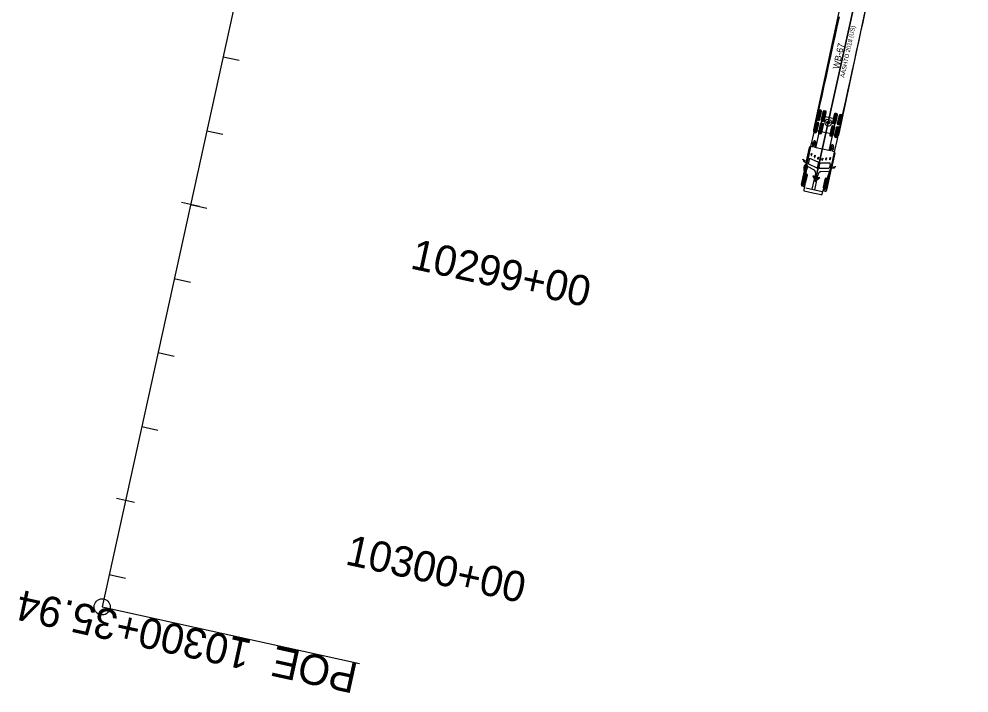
# Model space of a CAD drawing. Extents: x -69 to 14108008, y -6 to 8640172.
# Drawn here: x 14107520.5 to 14107834.1, y 8638940.1 to 8639162.5 of the extents above; entities that cross this region are included whole.
import ezdxf

# ---------------------------------------------------------------- set-up
doc = ezdxf.new("R2010")
doc.units = 0
for name, color, linetype in [('Alignment', 7, 'Continuous'), ('AutoTurn', 7, 'Continuous'), ('TextAlignment', 7, 'Continuous'), ('TextAlignmentLrg', 7, 'Continuous'), ('TextAlignmentSml', 7, 'Continuous')]:
    doc.layers.add(name, color=color, linetype=linetype)

msp = doc.modelspace()

# ---------------------------------------------------------------- linework, layer by layer
at = {"layer": 'Alignment'}
msp.add_line((14107732.61, 8639808.61), (14107547.95, 8638968.47), dxfattribs=at)
at = {"layer": 'AutoTurn'}
for p, q in [((14107783.36, 8639108.95), (14107834.09, 8639339.91)), ((14107834.09, 8639339.91), (14107783.36, 8639108.95)), ((14107783.91, 8639129.07), (14107784.7, 8639132.65)), ((14107784.14, 8639129.02), (14107784.92, 8639132.6)), ((14107784.36, 8639128.97), (14107785.15, 8639132.55)), ((14107785.53, 8639128.71), (14107786.31, 8639132.3)), ((14107785.75, 8639128.66), (14107786.54, 8639132.25)), ((14107785.97, 8639128.62), (14107786.76, 8639132.2)), ((14107789.22, 8639127.9), (14107790.01, 8639131.48)), ((14107789.44, 8639127.85), (14107790.23, 8639131.43)), ((14107789.67, 8639127.8), (14107790.46, 8639131.38)), ((14107790.83, 8639127.55), (14107791.62, 8639131.13)), ((14107791.06, 8639127.5), (14107791.84, 8639131.08)), ((14107791.28, 8639127.45), (14107792.07, 8639131.03)), ((14107783.01, 8639124.97), (14107783.8, 8639128.55)), ((14107783.24, 8639124.92), (14107784.02, 8639128.5)), ((14107783.46, 8639124.87), (14107784.25, 8639128.45)), ((14107784.62, 8639124.61), (14107785.41, 8639128.19)), ((14107784.85, 8639124.56), (14107785.63, 8639128.14)), ((14107785.07, 8639124.51), (14107785.86, 8639128.09)), ((14107788.58, 8639129), (14107787, 8639129.34)), ((14107788.32, 8639123.8), (14107789.11, 8639127.38)), ((14107788.54, 8639123.75), (14107789.33, 8639127.33)), ((14107788.77, 8639123.7), (14107789.55, 8639127.28)), ((14107789.93, 8639123.45), (14107790.72, 8639127.03)), ((14107790.15, 8639123.4), (14107790.94, 8639126.98)), ((14107790.38, 8639123.35), (14107791.17, 8639126.93)), ((14107781.83, 8639120.55), (14107782.66, 8639120.37)), ((14107781.96, 8639117.63), (14107782.12, 8639118.16)), ((14107782.12, 8639118.16), (14107782.2, 8639118.14)), ((14107782.2, 8639118.14), (14107782.12, 8639117.6)), ((14107783.6, 8639120.16), (14107787.83, 8639119.23)), ((14107788.78, 8639119.02), (14107789.6, 8639118.84)), ((14107779.54, 8639115.76), (14107779.52, 8639115.78)), ((14107779.57, 8639115.76), (14107779.54, 8639115.76)), ((14107780.34, 8639115.05), (14107780.32, 8639114.95)), ((14107780.83, 8639117.25), (14107780.54, 8639114.46)), ((14107781.3, 8639116.17), (14107781.06, 8639115.07)), ((14107781.14, 8639114.67), (14107783.87, 8639113.41)), ((14107784.3, 8639115.23), (14107781.57, 8639116.49)), ((14107783.07, 8639116.99), (14107783.22, 8639117.52)), ((14107783.22, 8639117.52), (14107783.31, 8639117.5)), ((14107783.31, 8639117.5), (14107783.23, 8639116.96)), ((14107784.14, 8639113.73), (14107784.38, 8639114.83)), ((14107784.18, 8639116.41), (14107784.34, 8639116.93)), ((14107784.34, 8639116.93), (14107784.43, 8639116.91)), ((14107784.43, 8639116.91), (14107784.35, 8639116.37)), ((14107784.65, 8639113.62), (14107784.89, 8639114.72)), ((14107784.81, 8639115.95), (14107784.96, 8639116.48)), ((14107784.96, 8639116.48), (14107785.05, 8639116.46)), ((14107785.05, 8639116.46), (14107784.97, 8639115.92)), ((14107785.13, 8639115.05), (14107788.14, 8639115.05)), ((14107785.56, 8639116.1), (14107785.72, 8639116.63)), ((14107785.72, 8639116.63), (14107785.81, 8639116.61)), ((14107785.81, 8639116.61), (14107785.73, 8639116.07)), ((14107789.13, 8639115.43), (14107785.82, 8639105.78)), ((14107786.82, 8639116.14), (14107786.98, 8639116.7)), ((14107786.98, 8639116.7), (14107787.07, 8639116.68)), ((14107787.07, 8639116.68), (14107786.98, 8639116.11)), ((14107788.25, 8639114.64), (14107788.01, 8639113.54)), ((14107788.1, 8639116.28), (14107788.25, 8639116.81)), ((14107788.25, 8639116.81), (14107788.34, 8639116.79)), ((14107788.34, 8639116.79), (14107788.26, 8639116.25)), ((14107778.76, 8639107.86), (14107779.76, 8639112.4)), ((14107779.28, 8639107.97), (14107780.07, 8639111.55)), ((14107779.5, 8639107.92), (14107780.29, 8639111.5)), ((14107779.73, 8639107.87), (14107780.51, 8639111.45)), ((14107780.34, 8639112.5), (14107779.79, 8639107.1)), ((14107783.08, 8639112.67), (14107780.79, 8639113.82)), ((14107787.77, 8639113.21), (14107784.76, 8639113.21)), ((14107785.17, 8639112.21), (14107787.71, 8639112.3)), ((14107788.65, 8639113.23), (14107788.62, 8639113.13)), ((14107789.65, 8639113.54), (14107789.67, 8639113.54)), ((14107789.67, 8639113.54), (14107789.7, 8639113.55)), ((14107782.35, 8639106.31), (14107783.4, 8639111.09)), ((14107783.16, 8639106.13), (14107784.21, 8639110.91)), ((14107786.2, 8639106.45), (14107786.98, 8639110.03)), ((14107786.42, 8639106.4), (14107787.21, 8639109.98)), ((14107786.65, 8639106.35), (14107787.43, 8639109.93)), ((14107779.23, 8639108.08), (14107779.16, 8639107.73)), ((14107779.16, 8639107.73), (14107779.56, 8639107.64)), ((14107779.63, 8639107.99), (14107779.23, 8639108.08)), ((14107779.56, 8639107.64), (14107779.63, 8639107.99)), ((14107780.18, 8639106.78), (14107785.61, 8639105.59)), ((14107786.25, 8639106.17), (14107786.33, 8639106.52)), ((14107786.66, 8639106.08), (14107786.25, 8639106.17)), ((14107786.33, 8639106.52), (14107786.73, 8639106.43)), ((14107786.73, 8639106.43), (14107786.66, 8639106.08))]:
    msp.add_line(p, q, dxfattribs=at)
for points in [[(14107793.83, 8639177.71), (14107793.81, 8639177.71), (14107793.79, 8639177.65), (14107792.61, 8639172.1), (14107782.76, 8639125.95), (14107786.91, 8639125.06), (14107791.07, 8639124.18), (14107800.92, 8639170.33), (14107802.1, 8639175.87), (14107802.12, 8639175.94), (14107802.1, 8639175.95)], [(14107799.71, 8639164.77), (14107799, 8639161.52), (14107798.28, 8639158.26), (14107797.57, 8639155), (14107796.85, 8639151.74), (14107796.14, 8639148.49), (14107795.42, 8639145.23), (14107794.7, 8639141.97), (14107793.99, 8639138.71), (14107793.27, 8639135.46), (14107792.56, 8639132.2), (14107791.84, 8639128.94), (14107791.13, 8639125.68), (14107790.41, 8639122.43), (14107789.7, 8639119.17), (14107788.98, 8639115.91), (14107788.26, 8639112.65), (14107787.55, 8639109.4), (14107787.26, 8639108.09)], [(14107791.18, 8639163.23), (14107790.47, 8639159.98), (14107789.75, 8639156.72), (14107789.04, 8639153.46), (14107788.32, 8639150.2), (14107787.61, 8639146.95), (14107786.89, 8639143.69), (14107786.18, 8639140.43), (14107785.46, 8639137.17), (14107784.74, 8639133.92), (14107784.03, 8639130.66), (14107783.31, 8639127.4), (14107782.6, 8639124.14), (14107781.88, 8639120.89), (14107781.17, 8639117.63), (14107780.45, 8639114.37), (14107779.74, 8639111.11), (14107779.45, 8639109.81)], [(14107782.93, 8639120.31), (14107783.6, 8639120.16), (14107783.65, 8639120.39), (14107785.88, 8639130.51), (14107787.99, 8639130.05), (14107790.11, 8639129.58), (14107787.88, 8639119.46), (14107787.83, 8639119.23), (14107788.5, 8639119.08)], [(14107779.5, 8639115.7), (14107779.52, 8639115.78), (14107779.52, 8639115.79), (14107779.26, 8639116.09), (14107779.26, 8639116.09), (14107779.29, 8639116.21), (14107779.29, 8639116.21), (14107779.94, 8639115.8), (14107779.91, 8639115.7), (14107779.57, 8639115.76), (14107779.57, 8639115.76), (14107779.55, 8639115.68), (14107779.55, 8639115.68), (14107779.55, 8639115.68), (14107779.56, 8639115.64), (14107779.56, 8639115.64), (14107780.34, 8639115.05), (14107781.45, 8639120.11)], [(14107789.76, 8639118.28), (14107788.65, 8639113.23), (14107789.61, 8639113.43), (14107789.61, 8639113.43), (14107789.63, 8639113.46), (14107789.63, 8639113.47), (14107789.63, 8639113.47), (14107789.65, 8639113.54), (14107789.65, 8639113.55), (14107789.31, 8639113.64), (14107789.33, 8639113.74), (14107790.09, 8639113.83), (14107790.09, 8639113.83), (14107790.07, 8639113.72), (14107790.06, 8639113.71), (14107789.7, 8639113.55), (14107789.7, 8639113.55), (14107789.68, 8639113.46)], [(14107780.23, 8639114.53), (14107780.32, 8639114.95), (14107780.31, 8639114.96), (14107779.52, 8639115.56)], [(14107789.61, 8639113.34), (14107788.63, 8639113.13), (14107788.62, 8639113.12), (14107787.07, 8639106.04)], [(14107783.36, 8639108.95), (14107784.89, 8639110.24), (14107783.57, 8639109.93), (14107782.51, 8639110.76), (14107783.36, 8639108.95)], [(14107786.67, 8639105.59), (14107785.83, 8639105.77), (14107785.82, 8639105.77), (14107785.36, 8639104.42), (14107785.29, 8639104.43), (14107782.5, 8639105.05), (14107779.7, 8639105.66), (14107779.64, 8639105.67), (14107779.79, 8639107.1), (14107779.78, 8639107.1), (14107778.94, 8639107.29)]]:
    msp.add_lwpolyline(points, dxfattribs=at)
for points in [[(14107784.42, 8639128.96), (14107783.86, 8639129.08), (14107783.8, 8639129.62), (14107784.37, 8639132.2), (14107784.65, 8639132.66), (14107785.2, 8639132.54), (14107785.26, 8639132), (14107784.7, 8639129.42)], [(14107786.03, 8639128.6), (14107785.47, 8639128.73), (14107785.41, 8639129.26), (14107785.98, 8639131.84), (14107786.26, 8639132.31), (14107786.82, 8639132.18), (14107786.87, 8639131.65), (14107786.31, 8639129.07)], [(14107789.72, 8639127.79), (14107789.17, 8639127.91), (14107789.11, 8639128.45), (14107789.67, 8639131.03), (14107789.95, 8639131.5), (14107790.51, 8639131.37), (14107790.57, 8639130.83), (14107790, 8639128.26)], [(14107791.34, 8639127.44), (14107790.78, 8639127.56), (14107790.72, 8639128.1), (14107791.29, 8639130.68), (14107791.56, 8639131.14), (14107792.12, 8639131.02), (14107792.18, 8639130.48), (14107791.61, 8639127.9)], [(14107783.52, 8639124.86), (14107782.96, 8639124.98), (14107782.9, 8639125.52), (14107783.47, 8639128.09), (14107783.74, 8639128.56), (14107784.3, 8639128.44), (14107784.36, 8639127.9), (14107783.79, 8639125.32)], [(14107785.13, 8639124.5), (14107784.57, 8639124.62), (14107784.51, 8639125.16), (14107785.08, 8639127.74), (14107785.36, 8639128.21), (14107785.91, 8639128.08), (14107785.97, 8639127.54), (14107785.41, 8639124.97)], [(14107788.82, 8639123.69), (14107788.26, 8639123.81), (14107788.21, 8639124.35), (14107788.77, 8639126.93), (14107789.05, 8639127.39), (14107789.61, 8639127.27), (14107789.67, 8639126.73), (14107789.1, 8639124.15)], [(14107790.43, 8639123.34), (14107789.88, 8639123.46), (14107789.82, 8639124), (14107790.38, 8639126.57), (14107790.66, 8639127.04), (14107791.22, 8639126.92), (14107791.28, 8639126.38), (14107790.71, 8639123.8)], [(14107779.78, 8639107.86), (14107779.22, 8639107.98), (14107779.17, 8639108.52), (14107779.73, 8639111.1), (14107780.01, 8639111.56), (14107780.57, 8639111.44), (14107780.63, 8639110.9), (14107780.06, 8639108.32)], [(14107783.36, 8639108.95), (14107784.89, 8639110.24), (14107783.57, 8639109.93), (14107782.51, 8639110.76)], [(14107786.7, 8639106.34), (14107786.14, 8639106.46), (14107786.08, 8639107), (14107786.65, 8639109.58), (14107786.93, 8639110.04), (14107787.49, 8639109.92), (14107787.55, 8639109.38), (14107786.98, 8639106.8)]]:
    msp.add_lwpolyline(points, close=True, dxfattribs=at)
for centre, radius in [((14107787.62, 8639128.38), 0.424), ((14107779.45, 8639109.81), 0.0417), ((14107783.36, 8639108.95), 0.0417), ((14107787.26, 8639108.09), 0.0417)]:
    msp.add_circle(centre, radius, dxfattribs=at)
for centre, radius, start, end in [((14107787.62, 8639128.38), 1.14, 122.6103, 32.6103), ((14107783.55, 8639121.07), 1.14, 163.1891, 217.9804), ((14107783.86, 8639121.14), 1.42, 132.6143, 169.6822), ((14107783.25, 8639121.17), 0.522, 165.4408, 212.6049), ((14107783.4, 8639121.22), 0.664, 134.4848, 172.7065), ((14107782.94, 8639121), 0.169, 219.0573, 319.176), ((14107783.14, 8639121.94), 0.346, 37.2046, 134.2176), ((14107783.06, 8639121.58), 0.172, 50.1581, 137.3087), ((14107782.54, 8639121.39), 0.732, 316.202, 2.4365), ((14107782.91, 8639121.46), 0.362, 354.2728, 43.3137), ((14107781.85, 8639121.54), 1.73, 328.9852, 353.7837), ((14107782.45, 8639121.55), 1.14, 350.3256, 31.8463), ((14107789.46, 8639120.01), 1.14, 123.3743, 164.895), ((14107788.99, 8639120.65), 0.346, 21.003, 118.0161), ((14107782.06, 8639119.97), 0.619, 111.7706, 167.6123), ((14107782.69, 8639121), 0.729, 289.2878, 331.8018), ((14107790, 8639119.75), 1.73, 161.4369, 186.2354), ((14107789.01, 8639119.61), 0.729, 183.4188, 225.9328), ((14107789.31, 8639119.91), 0.732, 152.7841, 199.0186), ((14107788.78, 8639119.72), 0.169, 196.0446, 296.1633), ((14107789, 8639120.12), 0.362, 111.9069, 160.9478), ((14107788.26, 8639120.03), 1.14, 297.2402, 352.0315), ((14107788.57, 8639120), 0.522, 302.6157, 349.7798), ((14107788.91, 8639120.29), 0.172, 17.9119, 105.0625), ((14107788.45, 8639120.11), 0.664, 342.5141, 20.7358), ((14107788.01, 8639120.23), 1.42, 345.5385, 22.6063), ((14107789.15, 8639118.42), 0.619, 347.6083, 43.45), ((14107779.57, 8639115.62), 0.108, 130.5866, 176.7691), ((14107779.52, 8639115.61), 0.0522, 166.4929, 271.3475), ((14107781.04, 8639113.23), 1.53, 122.103, 213.1121), ((14107780.32, 8639114.19), 0.347, 49.9375, 104.7481), ((14107781.42, 8639114.94), 0.387, 160.0455, 223.2775), ((14107781.63, 8639116.16), 0.332, 100.2669, 178.6889), ((14107782.09, 8639117.55), 0.157, 146.9547, 234.0643), ((14107781.94, 8639117.59), 0.184, 288.7651, 0.6571), ((14107783.2, 8639116.91), 0.157, 146.9547, 234.0643), ((14107783.05, 8639116.96), 0.184, 288.7651, 0.6571), ((14107784.32, 8639116.32), 0.157, 146.9547, 234.0643), ((14107784.16, 8639116.37), 0.184, 288.7651, 0.6571), ((14107784.02, 8639114.97), 0.387, 340.0479, 43.275), ((14107784.94, 8639115.87), 0.157, 146.9547, 234.0643), ((14107784.82, 8639115.89), 0.157, 281.1563, 8.2659), ((14107785.27, 8639114.69), 0.387, 111.9456, 175.1727), ((14107785.73, 8639116.02), 0.184, 154.5635, 226.4555), ((14107785.57, 8639116.04), 0.157, 281.1563, 8.2659), ((14107786.99, 8639116.09), 0.184, 154.5635, 226.4555), ((14107786.83, 8639116.11), 0.157, 281.1563, 8.2659), ((14107788.26, 8639116.2), 0.184, 154.5635, 226.4555), ((14107788.11, 8639116.22), 0.157, 281.1563, 8.2659), ((14107787.94, 8639114.78), 0.332, 336.5317, 54.9537), ((14107780.37, 8639113.28), 0.634, 158.1942, 234.1959), ((14107780, 8639112.76), 0.425, 235.6732, 322.2096), ((14107780.8, 8639113.32), 1.03, 140.434, 168.8205), ((14107780.54, 8639113.35), 0.589, 140.3658, 183.3485), ((14107780.17, 8639113.29), 0.223, 174.8452, 244.4477), ((14107780.26, 8639113.79), 0.317, 83.4605, 145.0529), ((14107780.03, 8639113.13), 0.366, 265.6626, 338.1436), ((14107780.21, 8639113.61), 0.17, 85.2794, 139.3437), ((14107780.1, 8639113.25), 0.158, 262.5815, 324.0943), ((14107779.78, 8639113.52), 0.575, 320.6854, 357.2558), ((14107780.1, 8639113.55), 0.263, 346.5452, 60.4471), ((14107780.1, 8639113.71), 0.44, 359.4045, 63.2174), ((14107779.08, 8639113.65), 1.7, 317.531, 353.4391), ((14107779.35, 8639113.61), 1.19, 328.7415, 4.6308), ((14107779.67, 8639113.73), 1.14, 346.3148, 40.1174), ((14107781.98, 8639111.62), 1.52, 339.1903, 43.6178), ((14107783.84, 8639113.71), 0.296, 274.3291, 4.6267), ((14107785.73, 8639110.8), 1.52, 111.6028, 176.0303), ((14107784.9, 8639113.47), 0.296, 150.5939, 240.8915), ((14107787.62, 8639113.57), 0.387, 291.9432, 355.1751), ((14107789.63, 8639113.39), 0.0522, 243.8731, 348.7277), ((14107789.58, 8639113.42), 0.108, 338.4515, 24.634), ((14107779.22, 8639107.69), 0.486, 159.1962, 235.1473), ((14107786.58, 8639106.07), 0.486, 280.0733, 356.0244)]:
    msp.add_arc(centre, radius, start, end, dxfattribs=at)
for centre, major_axis, start_param, end_param in [((14107779.51, 8639115.63), (-0.0168, -0.0764), 2.398717, 3.668019), ((14107779.51, 8639115.63), (-0.0168, -0.0764), 0.569648, 1.840391), ((14107789.64, 8639113.4), (0.0168, 0.0764), 1.301202, 2.571945), ((14107789.64, 8639113.4), (-0.0168, -0.0764), 2.615166, 3.884468)]:
    msp.add_ellipse(centre, major_axis=major_axis, ratio=0.544872, start_param=start_param, end_param=end_param, dxfattribs=at)
at = {"layer": 'TextAlignment'}
msp.add_line((14107547.95, 8638968.47), (14107632.92, 8638949.79), dxfattribs=at)
msp.add_circle((14107547.95, 8638968.47), 2.67, dxfattribs=at)
at = {"layer": 'TextAlignmentLrg'}
for p, q in [((14107577.13, 8639101.25), (14107582.46, 8639100.07)), ((14107558.65, 8639002.92), (14107552.67, 8639004.23))]:
    msp.add_line(p, q, dxfattribs=at)
at = {"layer": 'TextAlignmentSml'}
for p, q in [((14107587.86, 8639150.08), (14107593.2, 8639148.91)), ((14107582.5, 8639125.66), (14107587.83, 8639124.49)), ((14107580.12, 8639100.59), (14107574.14, 8639101.9)), ((14107571.76, 8639076.83), (14107577.1, 8639075.66)), ((14107566.4, 8639052.41), (14107571.73, 8639051.24)), ((14107561.03, 8639027.99), (14107566.36, 8639026.82)), ((14107558.65, 8639002.92), (14107552.67, 8639004.23)), ((14107550.3, 8638979.16), (14107555.63, 8638977.99))]:
    msp.add_line(p, q, dxfattribs=at)

# ---------------------------------------------------------------- texts
at = {"layer": 'AutoTurn'}
for s, height, p in [('AASHTO 2018 (US)', 1.4167, (14107792.93, 8639143.04)), ('WB-67', 2.125, (14107791.17, 8639145.82)), ('(c) 2023 Transoft Solutions, Inc. All rights reserved.', 0.085, (14107792.12, 8639149.27))]:
    msp.add_text(s, height=height, rotation=77.9529, dxfattribs=at).set_placement(p)
at = {"layer": 'TextAlignment'}
for s, p in [('10300+35.94', (14107597.78, 8638957.32)), ('POE ', (14107632.88, 8638949.6))]:
    msp.add_text(s, height=10.02, rotation=167.6032, dxfattribs=at).set_placement(p)
at = {"layer": 'TextAlignmentLrg'}
msp.add_text('10300+00', height=10.02, rotation=347.6032, dxfattribs=at).set_placement((14107627.84, 8638982.58))
at = {"layer": 'TextAlignmentSml'}
for s, p in [('10299+00', (14107649.31, 8639080.25)), ('10300+00', (14107627.84, 8638982.58))]:
    msp.add_text(s, height=10.02, rotation=347.6032, dxfattribs=at).set_placement(p)

doc.saveas('drawing.dxf')
